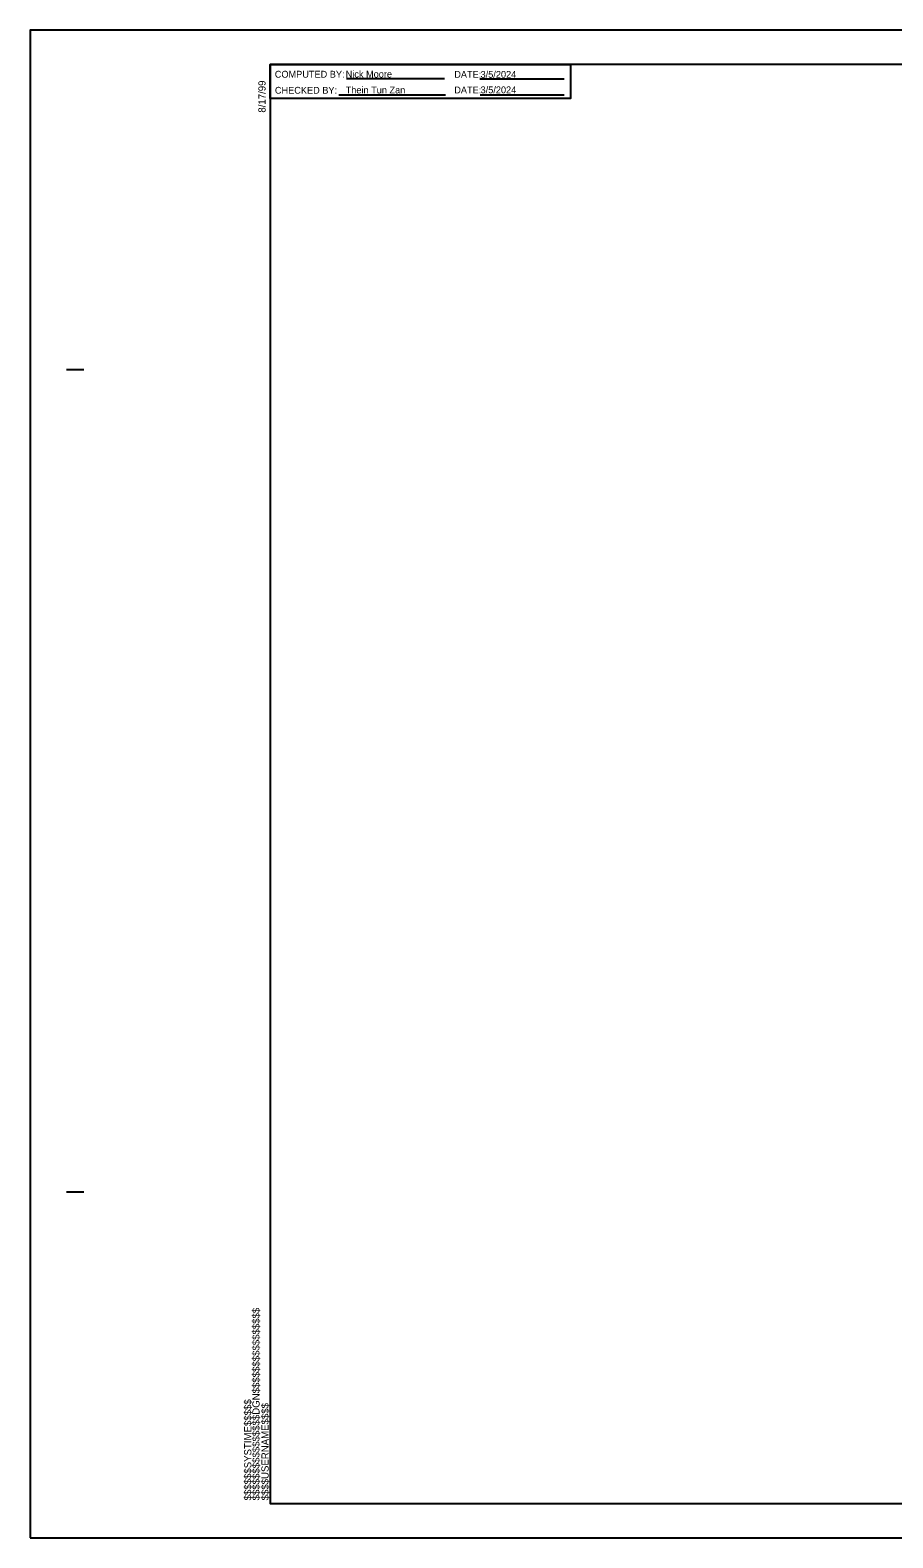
# Model space of a CAD drawing. Extents: x 573680 to 575380, y -54660 to -53560.
# Drawn here: x 573680 to 574309, y -54660 to -53560 of the extents above; entities that cross this region are included whole.
import ezdxf

# ---------------------------------------------------------------- set-up
doc = ezdxf.new("R2010")
doc.units = 0
for name, color, linetype in [('Sheet Block System Information CELL', 7, 'Continuous'), ('Sheet Data Field CELL', 7, 'Continuous'), ('Sheet Plan And Profile CELL', 7, 'Continuous'), ('Sheet Plot Border Outside CELL', 7, 'Continuous'), ('Sheet Summary Guardrail CELL', 7, 'Continuous')]:
    doc.layers.add(name, color=color, linetype=linetype)

msp = doc.modelspace()

# ---------------------------------------------------------------- linework, layer by layer
at = {"layer": 'Sheet Block System Information CELL'}
msp.add_line((573854.9, -54634.7), (573854.9, -54634.7), dxfattribs=at)
at = {"layer": 'Sheet Plan And Profile CELL'}
for p, q in [((573706.4, -53807.2), (573718.9, -53807.2)), ((573706.4, -54407.2), (573718.9, -54407.2)), ((573854.9, -54634.7), (573854.9, -54634.7)), ((573854.9, -54634.7), (573854.9, -54634.7)), ((573854.9, -54634.7), (573854.9, -54634.7)), ((573854.9, -54634.7), (573854.9, -54634.7)), ((573854.9, -54634.7), (573854.9, -54634.7))]:
    msp.add_line(p, q, dxfattribs=at)
msp.add_lwpolyline([(575354.9, -53584.7), (573854.9, -53584.7), (573854.9, -54634.7), (575354.9, -54634.7)], close=True, dxfattribs=at)
at = {"layer": 'Sheet Plot Border Outside CELL'}
msp.add_lwpolyline([(573679.9, -54659.7), (575379.9, -54659.7), (575379.9, -53559.7), (573679.9, -53559.7)], close=True, dxfattribs=at)
at = {"layer": 'Sheet Summary Guardrail CELL'}
for p, q in [((573910.5, -53595.1), (573982.1, -53595.1)), ((574007.9, -53595.3), (574069.3, -53595.3)), ((573905.1, -53606.8), (573982.8, -53606.8)), ((574008, -53606.8), (574069.4, -53606.8))]:
    msp.add_line(p, q, dxfattribs=at)
msp.add_lwpolyline([(573854.9, -53584.7), (574073.9, -53584.7), (574073.9, -53609.7), (573854.9, -53609.7)], close=True, dxfattribs=at)

# ---------------------------------------------------------------- texts
at = {"layer": 'Sheet Block System Information CELL'}
for s, p in [('$$$$$$$$$$$$$$$$DGN$$$$$$$$$$$$$$$$', (573847.2, -54632.4)), ('$$$$$$SYSTIME$$$$$', (573841.2, -54632.4)), ('$$$$USERNAME$$$$', (573853.8, -54632.4))]:
    msp.add_text(s, height=5.25, rotation=90, dxfattribs=at).set_placement(p)
at = {"layer": 'Sheet Data Field CELL'}
for s, p in [('Nick Moore', (573910, -53594.3)), ('3/5/2024', (574008.4, -53594.5)), ('Thein Tun Zan', (573910, -53605.9)), ('3/5/2024', (574008.4, -53605.8))]:
    msp.add_text(s, height=5, dxfattribs=at).set_placement(p)
at = {"layer": 'Sheet Plan And Profile CELL'}
msp.add_text('8/17/99', height=5.25, rotation=90, dxfattribs=at).set_placement((573851.6, -53619.9))
at = {"layer": 'Sheet Summary Guardrail CELL'}
for s, p in [('COMPUTED BY:', (573858.3, -53594.4)), ('DATE:', (573989.2, -53594.5)), ('CHECKED BY:', (573858.4, -53606.1)), ('DATE:', (573989.2, -53605.9))]:
    msp.add_text(s, height=5, dxfattribs=at).set_placement(p)

doc.saveas('drawing.dxf')
